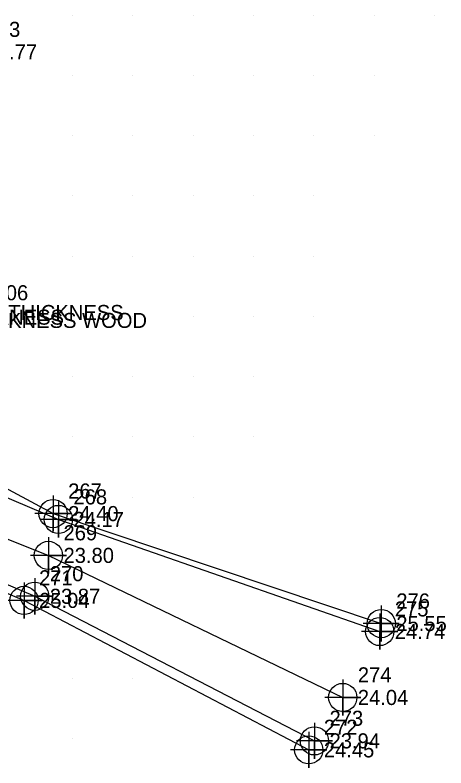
# Model space of a CAD drawing. Extents: x 2204340 to 2204783, y 268170 to 268760.
# Drawn here: x 2204570.5 to 2204641.9, y 268405.1 to 268530 of the extents above; entities that cross this region are included whole.
import ezdxf

# ---------------------------------------------------------------- set-up
doc = ezdxf.new("R2010")
doc.units = 0
for name, color, linetype in [('Exist DTM Breakline', 7, 'Continuous'), ('Exist DTM Breakline Cogo Elevation', 7, 'Continuous'), ('Exist DTM Breakline Cogo Number', 7, 'Continuous'), ('Exist DTM Breakline Cogo Point CELL', 7, 'Continuous'), ('Exist DTM Breakline Underwater', 7, 'Continuous'), ('Exist DTM Breakline Underwater Cogo Elevation', 7, 'Continuous'), ('Exist DTM Breakline Underwater Cogo Number', 7, 'Continuous'), ('Exist DTM Breakline Underwater Cogo Point CELL', 7, 'Continuous'), ('Exist DTM QL2 LIDAR Elevation Point', 7, 'Continuous'), ('Exist Hydro Jurisdictional Stream or Body of Water', 7, 'Continuous'), ('Exist Roads Change in Surface Cogo Comment', 7, 'Continuous'), ('Exist Roads Soil Cogo Elevation', 7, 'Continuous'), ('Exist Roads Soil Cogo Number', 7, 'Continuous'), ('Exist Structure Major Bridge WW Cogo Comment', 7, 'Continuous'), ('Exist Structure Major Bridge WW Cogo Elevation', 7, 'Continuous')]:
    doc.layers.add(name, color=color, linetype=linetype)

msp = doc.modelspace()

# ---------------------------------------------------------------- linework, layer by layer
at = {"layer": 'Exist DTM Breakline'}
for points in [[(2204442.11, 268518.11), (2204480.82, 268501.8), (2204502.53, 268495.78), (2204515.27, 268483.58), (2204555.41, 268455.78), (2204577.65, 268446.31), (2204630.94, 268427.72)], [(2204435.36, 268505.62), (2204480.45, 268489.14), (2204494.51, 268488.53), (2204511.37, 268475.79), (2204547.35, 268444.74), (2204573.73, 268433.57), (2204620.13, 268409.58)]]:
    msp.add_lwpolyline(points, dxfattribs=at)
at = {"layer": 'Exist DTM Breakline Cogo Point CELL'}
for points in [[(2204576.77, 268450.29), (2204576.77, 268444.29), (2204576.77, 268447.29), (2204579.77, 268447.29), (2204573.77, 268447.29)], [(2204577.65, 268449.31), (2204577.65, 268443.31), (2204577.65, 268446.31), (2204580.65, 268446.31), (2204574.65, 268446.31)], [(2204573.73, 268436.57), (2204573.73, 268430.57), (2204573.73, 268433.57), (2204576.73, 268433.57), (2204570.73, 268433.57)], [(2204571.95, 268435.88), (2204571.95, 268429.88), (2204571.95, 268432.88), (2204574.95, 268432.88), (2204568.95, 268432.88)], [(2204631.19, 268432.04), (2204631.19, 268426.04), (2204631.19, 268429.04), (2204634.19, 268429.04), (2204628.19, 268429.04)], [(2204630.94, 268430.72), (2204630.94, 268424.72), (2204630.94, 268427.72), (2204633.94, 268427.72), (2204627.94, 268427.72)], [(2204620.12, 268412.58), (2204620.12, 268406.58), (2204620.12, 268409.58), (2204623.12, 268409.58), (2204617.12, 268409.58)], [(2204619.17, 268411.09), (2204619.17, 268405.09), (2204619.17, 268408.09), (2204622.17, 268408.09), (2204616.17, 268408.09)]]:
    msp.add_lwpolyline(points, dxfattribs=at)
for centre in [(2204576.77, 268447.29), (2204577.65, 268446.31), (2204571.95, 268432.88), (2204573.73, 268433.57), (2204631.19, 268429.04), (2204630.94, 268427.72), (2204620.12, 268409.58), (2204619.17, 268408.09)]:
    msp.add_circle(centre, 2.34, dxfattribs=at)
at = {"layer": 'Exist DTM Breakline Underwater'}
msp.add_lwpolyline([(2204438.58, 268512.92), (2204481.57, 268495.84), (2204497.2, 268490.9), (2204514.25, 268479.67), (2204552.14, 268449.92), (2204576, 268440.35), (2204624.81, 268416.78)], dxfattribs=at)
at = {"layer": 'Exist DTM Breakline Underwater Cogo Point CELL'}
for points in [[(2204576, 268443.35), (2204576, 268437.35), (2204576, 268440.35), (2204579, 268440.35), (2204573, 268440.35)], [(2204624.81, 268419.78), (2204624.81, 268413.78), (2204624.81, 268416.78), (2204627.81, 268416.78), (2204621.81, 268416.78)]]:
    msp.add_lwpolyline(points, dxfattribs=at)
for centre in [(2204576, 268440.35), (2204624.81, 268416.78)]:
    msp.add_circle(centre, 2.34, dxfattribs=at)
at = {"layer": 'Exist DTM QL2 LIDAR Elevation Point'}
for p, q in [((2204580, 268530), (2204580, 268530)), ((2204590, 268530), (2204590, 268530)), ((2204600, 268530), (2204600, 268530)), ((2204610, 268530), (2204610, 268530)), ((2204620, 268530), (2204620, 268530)), ((2204630, 268530), (2204630, 268530)), ((2204640, 268530), (2204640, 268530)), ((2204580, 268520), (2204580, 268520)), ((2204590, 268520), (2204590, 268520)), ((2204600, 268520), (2204600, 268520)), ((2204610, 268520), (2204610, 268520)), ((2204620, 268520), (2204620, 268520)), ((2204630, 268520), (2204630, 268520)), ((2204580, 268510), (2204580, 268510)), ((2204590, 268510), (2204590, 268510)), ((2204600, 268510), (2204600, 268510)), ((2204610, 268510), (2204610, 268510)), ((2204620, 268510), (2204620, 268510)), ((2204630, 268510), (2204630, 268510)), ((2204580, 268500), (2204580, 268500)), ((2204590, 268500), (2204590, 268500)), ((2204600, 268500), (2204600, 268500)), ((2204610, 268500), (2204610, 268500)), ((2204620, 268500), (2204620, 268500)), ((2204580, 268490), (2204580, 268490)), ((2204590, 268490), (2204590, 268490)), ((2204600, 268490), (2204600, 268490)), ((2204610, 268490), (2204610, 268490)), ((2204620, 268490), (2204620, 268490)), ((2204580, 268480), (2204580, 268480)), ((2204590, 268480), (2204590, 268480)), ((2204600, 268480), (2204600, 268480)), ((2204610, 268480), (2204610, 268480)), ((2204620, 268480), (2204620, 268480)), ((2204580, 268470), (2204580, 268470)), ((2204590, 268470), (2204590, 268470)), ((2204600, 268470), (2204600, 268470)), ((2204610, 268470), (2204610, 268470)), ((2204580, 268460), (2204580, 268460)), ((2204590, 268460), (2204590, 268460)), ((2204600, 268460), (2204600, 268460)), ((2204610, 268460), (2204610, 268460)), ((2204580, 268450), (2204580, 268450)), ((2204590, 268450), (2204590, 268450)), ((2204600, 268450), (2204600, 268450)), ((2204580, 268420), (2204580, 268420)), ((2204590, 268420), (2204590, 268420)), ((2204580, 268410), (2204580, 268410))]:
    msp.add_line(p, q, dxfattribs=at)
at = {"layer": 'Exist Hydro Jurisdictional Stream or Body of Water'}
for points in [[(2204442.88, 268520.11), (2204480.52, 268503.56), (2204503.23, 268495.9), (2204516.01, 268483.84), (2204556.67, 268458.09), (2204576.77, 268447.29), (2204631.19, 268429.04)], [(2204434.67, 268504.23), (2204475.09, 268482.79), (2204492.09, 268478.07), (2204511.02, 268474.48), (2204547.96, 268443.09), (2204571.96, 268432.88), (2204619.17, 268408.09)]]:
    msp.add_lwpolyline(points, dxfattribs=at)

# ---------------------------------------------------------------- texts
at = {"layer": 'Exist DTM Breakline Cogo Elevation'}
for s, p in [('24.40', (2204579.27, 268446.04)), ('24.17', (2204580.15, 268445.06)), ('23.87', (2204576.23, 268432.32)), ('25.04', (2204574.45, 268431.63)), ('25.55', (2204633.69, 268427.79)), ('24.74', (2204633.44, 268426.47)), ('23.94', (2204622.62, 268408.33)), ('24.45', (2204621.67, 268406.84))]:
    msp.add_text(s, height=2.5, dxfattribs=at).set_placement(p)
at = {"layer": 'Exist DTM Breakline Cogo Number'}
for s, p in [('267', (2204579.27, 268449.79)), ('268', (2204580.15, 268448.81)), ('270', (2204576.23, 268436.07)), ('271', (2204574.45, 268435.38)), ('276', (2204633.69, 268431.54)), ('275', (2204633.44, 268430.22)), ('273', (2204622.62, 268412.08)), ('272', (2204621.67, 268410.59))]:
    msp.add_text(s, height=2.5, dxfattribs=at).set_placement(p)
at = {"layer": 'Exist DTM Breakline Underwater Cogo Elevation'}
for s, p in [('23.80', (2204578.5, 268439.1)), ('24.04', (2204627.31, 268415.53))]:
    msp.add_text(s, height=2.5, dxfattribs=at).set_placement(p)
at = {"layer": 'Exist DTM Breakline Underwater Cogo Number'}
for s, p in [('269', (2204578.5, 268442.85)), ('274', (2204627.31, 268419.28))]:
    msp.add_text(s, height=2.5, dxfattribs=at).set_placement(p)
at = {"layer": 'Exist Roads Change in Surface Cogo Comment'}
msp.add_text('.65WOODTHICKNESS', height=2.5, dxfattribs=at).set_placement((2204553.93, 268479.4))
at = {"layer": 'Exist Roads Soil Cogo Elevation'}
msp.add_text('32.77', height=2.5, dxfattribs=at).set_placement((2204565.75, 268522.63))
at = {"layer": 'Exist Roads Soil Cogo Number'}
msp.add_text('193', height=2.5, dxfattribs=at).set_placement((2204565.75, 268526.38))
at = {"layer": 'Exist Structure Major Bridge WW Cogo Comment'}
for s, p in [('.25THICKNESS', (2204554.81, 268478.63)), ('.65THICKNESS WOOD', (2204556.87, 268478.09))]:
    msp.add_text(s, height=2.5, dxfattribs=at).set_placement(p)
at = {"layer": 'Exist Structure Major Bridge WW Cogo Elevation'}
msp.add_text('30.06', height=2.5, dxfattribs=at).set_placement((2204564.28, 268482.68))

doc.saveas('drawing.dxf')
